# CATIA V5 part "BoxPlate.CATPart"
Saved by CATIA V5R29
Part number: BoxPlate
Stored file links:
  C:\Users\Administrator\Desktop\프로젝트\Boxfold\BoxPlate.CATPart
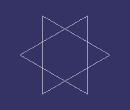
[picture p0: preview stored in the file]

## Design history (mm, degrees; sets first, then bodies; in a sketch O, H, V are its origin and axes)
Body1 (main body)
  DatumCurve1 to DatumCurve3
